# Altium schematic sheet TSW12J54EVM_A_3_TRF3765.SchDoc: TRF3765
size 431 x 279 mm; Date: Not shown in title block; ApprovedBy: Not shown in title block; CheckedBy: Not shown in title block; Author: Not shown in title block; CompanyName: Not shown in title block; DrawnBy: Not shown in title block; Engineer: Not shown in title block; Organization: Not shown in title block; Address1: Not shown in title block; Address2: Not shown in title block; Address3: Not shown in title block; Address4: Not shown in title block; DocumentNumber: 3; Revision: Use project parameter SCH_Rev; SheetNumber: 3; SheetTotal: 8; PageSetup: Record=PageOptions¦CenterHorizontal=True¦CenterVertical=True¦PrintScale=0.49¦XCorrection=1.00¦YCorrection=1.00¦PrintKind=0¦BorderSize=5000000¦LeftOffset=0¦BottomOffset=0¦Orientation=2¦PaperLength=1000¦PaperWidth=1000¦Scale=100¦PaperSource=15¦PrintQuality=600¦MediaType=1¦DitherType=10¦PaperKind=11x17¦PrintScaleMode=1
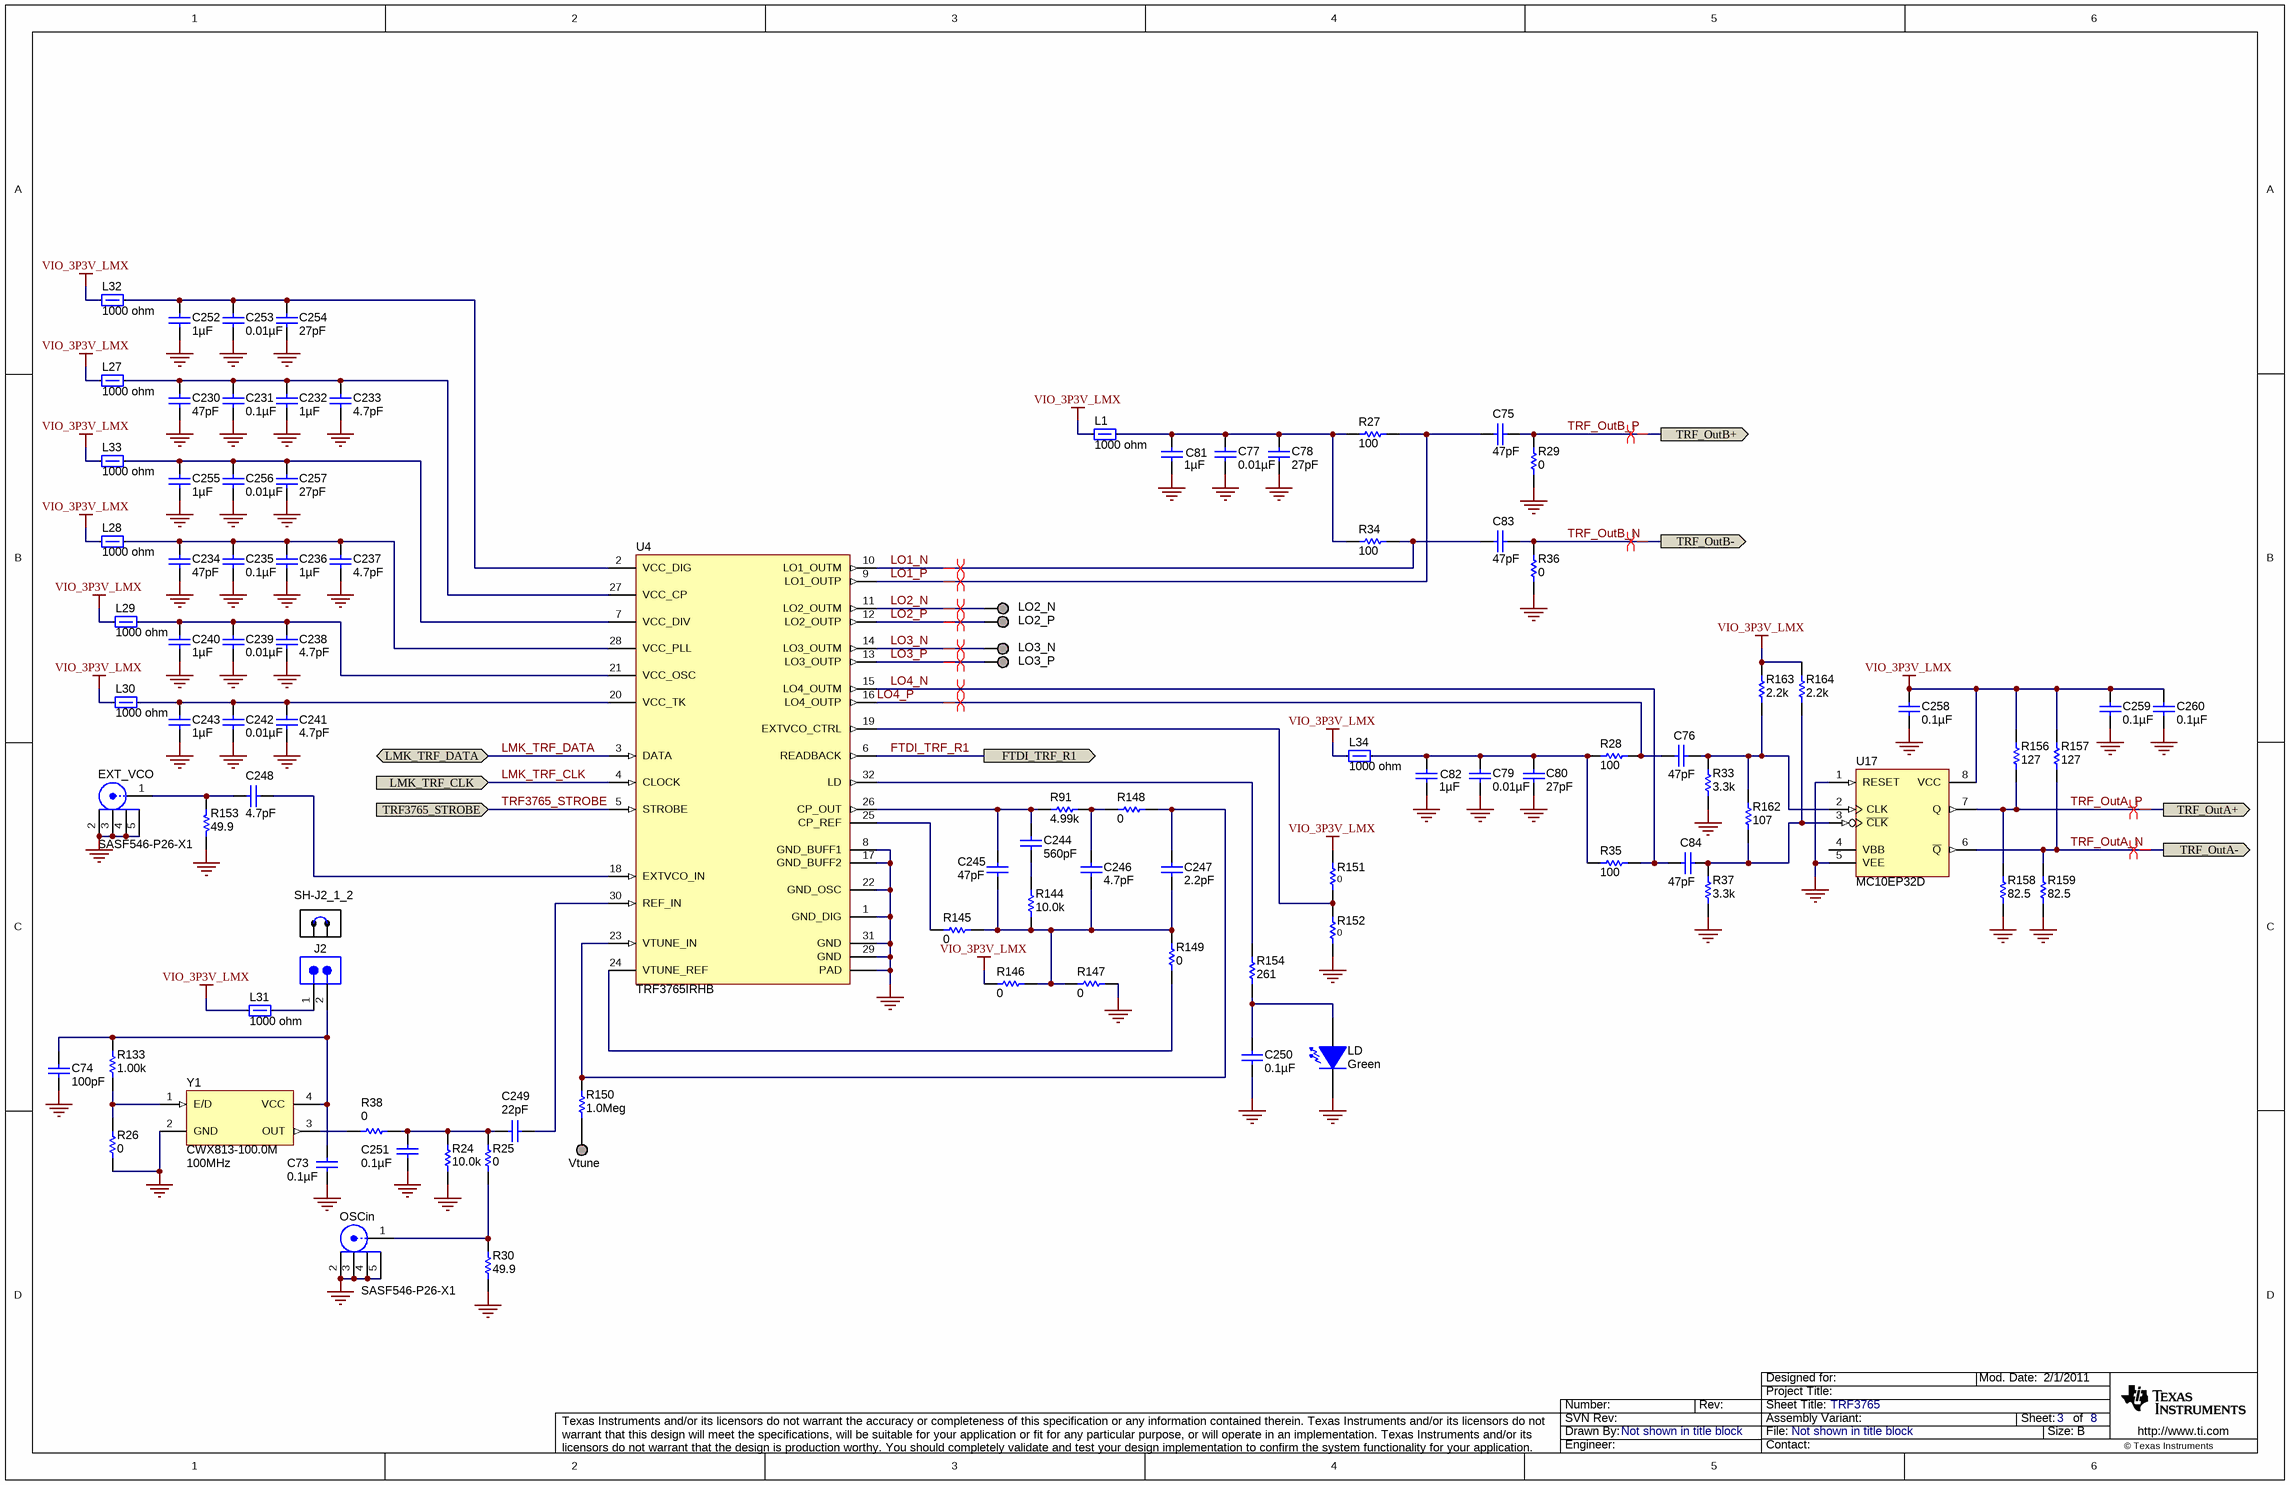
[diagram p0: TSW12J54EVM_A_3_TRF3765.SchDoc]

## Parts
C73  ValueDisplayed: 0.1µF  [0402L]  (hidden comment: C1005X5R1A104K)
C74  ValueDisplayed: 100pF  [0402L]  (hidden comment: GRM1555C1E101JA01D)
C75  ValueDisplayed: 47pF  [0402L]  (hidden comment: GRM1555C1H470JA01D)
C76  ValueDisplayed: 47pF  [0402L]  (hidden comment: GRM1555C1H470JA01D)
C77  ValueDisplayed: 0.01µF  [0402L]  (hidden comment: GRM155R71E103KA01D)
C78  ValueDisplayed: 27pF  [0402L]  (hidden comment: GRM1555C1H270JA01D)
C79  ValueDisplayed: 0.01µF  [0402L]  (hidden comment: GRM155R71E103KA01D)
C80  ValueDisplayed: 27pF  [0402L]  (hidden comment: GRM1555C1H270JA01D)
C81  ValueDisplayed: 1µF  [0402L]  (hidden comment: C1005X5R0J105M)
C82  ValueDisplayed: 1µF  [0402L]  (hidden comment: C1005X5R0J105M)
C83  ValueDisplayed: 47pF  [0402L]  (hidden comment: GRM1555C1H470JA01D)
C84  ValueDisplayed: 47pF  [0402L]  (hidden comment: GRM1555C1H470JA01D)
C230  ValueDisplayed: 47pF  [0603L]  (hidden comment: GRM1885C1H470JA01D)
C231  ValueDisplayed: 0.1µF  [0402L]  (hidden comment: C1005X5R1A104K)
C232  ValueDisplayed: 1µF  [0402L]  (hidden comment: C1005X5R0J105M)
C233  ValueDisplayed: 4.7pF  [0402L]  (hidden comment: GRM1555C1H4R7CA01D)
C234  ValueDisplayed: 47pF  [0603L]  (hidden comment: GRM1885C1H470JA01D)
C235  ValueDisplayed: 0.1µF  [0402L]  (hidden comment: C1005X5R1A104K)
C236  ValueDisplayed: 1µF  [0402L]  (hidden comment: C1005X5R0J105M)
C237  ValueDisplayed: 4.7pF  [0402L]  (hidden comment: GRM1555C1H4R7CA01D)
C238  ValueDisplayed: 4.7pF  [0402L]  (hidden comment: GRM1555C1H4R7CA01D)
C239  ValueDisplayed: 0.01µF  [0402L]  (hidden comment: GRM155R71E103KA01D)
C240  ValueDisplayed: 1µF  [0402L]  (hidden comment: C1005X5R0J105M)
C241  ValueDisplayed: 4.7pF  [0402L]  (hidden comment: GRM1555C1H4R7CA01D)
C242  ValueDisplayed: 0.01µF  [0402L]  (hidden comment: GRM155R71E103KA01D)
C243  ValueDisplayed: 1µF  [0402L]  (hidden comment: C1005X5R0J105M)
C244  ValueDisplayed: 560pF  [0402L]  (hidden comment: GRM1555C1H561JA01D)
C245  ValueDisplayed: 47pF  [0402L]  (hidden comment: GRM1555C1H470JA01D)
C246  ValueDisplayed: 4.7pF  [0402L]  (hidden comment: GRM1555C1H4R7CA01D)
C247  ValueDisplayed: 2.2pF  [0402L]  (hidden comment: GRM1555C1H2R2CA01D)
C248  ValueDisplayed: 4.7pF  [0402L]  (hidden comment: GRM1555C1H4R7CA01D)
C249  ValueDisplayed: 22pF  [0402L]  (hidden comment: GRM1555C1H220JA01D)
C250  ValueDisplayed: 0.1µF  [0402L]  (hidden comment: C1005X5R1A104K)
C251  ValueDisplayed: 0.1µF  [0402L]  (hidden comment: C1005X5R1A104K)
C252  ValueDisplayed: 1µF  [0402L]  (hidden comment: C1005X5R0J105M)
C253  ValueDisplayed: 0.01µF  [0402L]  (hidden comment: GRM155R71E103KA01D)
C254  ValueDisplayed: 27pF  [0402L]  (hidden comment: GRM1555C1H270JA01D)
C255  ValueDisplayed: 1µF  [0402L]  (hidden comment: C1005X5R0J105M)
C256  ValueDisplayed: 0.01µF  [0402L]  (hidden comment: GRM155R71E103KA01D)
C257  ValueDisplayed: 27pF  [0402L]  (hidden comment: GRM1555C1H270JA01D)
C258  ValueDisplayed: 0.1µF  [0402L]  (hidden comment: C1005X5R1A104K)
C259  ValueDisplayed: 0.1µF  [0402L]  (hidden comment: C1005X5R1A104K)
C260  ValueDisplayed: 0.1µF  [0402L]  (hidden comment: C1005X5R1A104K)
EXT_VCO  SASF546-P26-X1  [CONN_LTI_SASF546-P26-X1]
J2  TSW-102-07-G-S  [TSW-102-07-G-S]  (value not drawn)
L1  value 1000 ohm  [0402L]  (hidden comment: BLM15HG102SN1D)
L27  value 1000 ohm  [0402L]  (hidden comment: BLM15HG102SN1D)
L28  value 1000 ohm  [0402L]  (hidden comment: BLM15HG102SN1D)
L29  value 1000 ohm  [0402L]  (hidden comment: BLM15HG102SN1D)
L30  value 1000 ohm  [0402L]  (hidden comment: BLM15HG102SN1D)
L31  value 1000 ohm  [0402L]  (hidden comment: BLM15HG102SN1D)
L32  value 1000 ohm  [0402L]  (hidden comment: BLM15HG102SN1D)
L33  value 1000 ohm  [0402L]  (hidden comment: BLM15HG102SN1D)
L34  value 1000 ohm  [0402L]  (hidden comment: BLM15HG102SN1D)
LD  value Green  [LED_LTST-C190]  (hidden comment: LTST-C190GKT)
LO2_N  TESTPOINT  [TESTPOINT]  (value not drawn)  (no BOM)
LO2_P  TESTPOINT  [TESTPOINT]  (value not drawn)  (no BOM)
LO3_N  TESTPOINT  [TESTPOINT]  (value not drawn)  (no BOM)
LO3_P  TESTPOINT  [TESTPOINT]  (value not drawn)  (no BOM)
OSCin  SASF546-P26-X1  [CONN_LTI_SASF546-P26-X1]
R24  value 10.0k  [0402L]  (hidden comment: CRCW040210K0FKED)
R25  value 0  [0402L]  (hidden comment: ERJ-2GE0R00X)
R26  value 0  [0402L]  (hidden comment: ERJ-2GE0R00X)
R27  value 100  [0402L]  (hidden comment: CRCW0402100RFKED)
R28  value 100  [0402L]  (hidden comment: CRCW0402100RFKED)
R29  value 0  [0402L]  (hidden comment: ERJ-2GE0R00X)
R30  value 49.9  [0402L]  (hidden comment: CRCW040249R9FKED)
R33  value 3.3k  [0402L]  (hidden comment: CRCW04023K30JNED)
R34  value 100  [0402L]  (hidden comment: CRCW0402100RFKED)
R35  value 100  [0402L]  (hidden comment: CRCW0402100RFKED)
R36  value 0  [0402L]  (hidden comment: ERJ-2GE0R00X)
R37  value 3.3k  [0402L]  (hidden comment: CRCW04023K30JNED)
R38  value 0  [0402L]  (hidden comment: ERJ-2GE0R00X)
R91  value 4.99k  [0402L]  (hidden comment: CRCW04024K99FKED)
R133  value 1.00k  [0402L]  (hidden comment: CRCW04021K00FKED)
R144  value 10.0k  [0402L]  (hidden comment: CRCW040210K0FKED)
R145  value 0  [0402L]  (hidden comment: ERJ-2GE0R00X)
R146  value 0  [0402L]  (hidden comment: ERJ-2GE0R00X)
R147  value 0  [0402L]  (hidden comment: ERJ-2GE0R00X)
R148  value 0  [0402L]  (hidden comment: ERJ-2GE0R00X)
R149  value 0  [0402L]  (hidden comment: ERJ-2GE0R00X)
R150  value 1.0Meg  [0402L]  (hidden comment: CRCW04021M00JNED)
R151  value 0  [0603L]  (hidden comment: CRCW06030000Z0EA)
R152  value 0  [0603L]  (hidden comment: CRCW06030000Z0EA)
R153  value 49.9  [0402L]  (hidden comment: CRCW040249R9FKED)
R154  ValueDisplayed: 261  [0402L]  (hidden comment: CRCW0402261RFKED)
R156  value 127  [0402L]  (hidden comment: CRCW0402127RFKED)
R157  value 127  [0402L]  (hidden comment: CRCW0402127RFKED)
R158  value 82.5  [0402L]  (hidden comment: CRCW040282R5FKED)
R159  value 82.5  [0402L]  (hidden comment: CRCW040282R5FKED)
R162  value 107  [0402L]  (hidden comment: CRCW0402107RFKED)
R163  value 2.2k  [0402L]  (hidden comment: CRCW04022K20JNED)
R164  value 2.2k  [0402L]  (hidden comment: CRCW04022K20JNED)
SH-J2_1_2  SNT-100-BK-G  [SNT-100-BK-G]  (value not drawn)
U4  TRF3765IRHB  [RHB0032E]
U17  MC10EP32D  [751-06_N]
Vtune  TESTPOINT  [TESTPOINT]  (value not drawn)  (no BOM)
Y1  CWX813-100.0M  Frequency: 100MHz  [OSC_CWX]

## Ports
FTDI_TRF_R1, LMK_TRF_CLK, LMK_TRF_DATA (bidir), TRF3765_STROBE, TRF_OutA+ (out), TRF_OutA- (out), TRF_OutB+, TRF_OutB-

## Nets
GND: C73.1 C74.1 C77.2 C78.2 C79.2 C80.2 C81.2 C82.2 C230.2 C231.1 C232.2 C233.2 C234.2 C235.1 C236.2 C237.2 C238.2 C239.2 C240.2 C241.2 C242.2 C243.2 C250.1 C251.1 C252.2 C253.2 C254.2 C255.2 C256.2 C257.2 C258.1 C259.1 C260.1 EXT_VCO.2 EXT_VCO.3 EXT_VCO.4 EXT_VCO.5 LD.2(K) OSCin.2 OSCin.3 OSCin.4 OSCin.5 R24.1 R26.1 R29.1 R30.1 R33.1 R36.1 R37.1 R147.2 R152.2 R153.1 R158.1 R159.1 U4.1(GND_DIG) U4.8(GND_BUFF1) U4.17(GND_BUFF2) U4.22(GND_OSC) U4.29(GND) U4.31(GND) U4.33(PAD) U17.1(RESET) U17.5(VEE) Y1.2(GND)
VIO_3P3V_LMX: C258.2 C259.2 C260.2 L1.1 L27.1 L28.1 L29.1 L30.1 L31.1 L32.1 L33.1 L34.1 R146.1 R151.1 R156.2 R157.2 R163.2 R164.2 U17.8(VCC)
FTDI_TRF_R1: U4.6(READBACK) ; port FTDI_TRF_R1
LMK_TRF_CLK: U4.4(CLOCK) ; port LMK_TRF_CLK
LMK_TRF_DATA: U4.3(DATA) ; port LMK_TRF_DATA
LO1_N: C83.1 R34.2 U4.10(LO1_OUTM)
LO1_P: C75.1 R27.2 U4.9(LO1_OUTP)
LO2_N: LO2_N.1 U4.11(LO2_OUTM)
LO2_P: LO2_P.1 U4.12(LO2_OUTP)
LO3_N: LO3_N.1 U4.14(LO3_OUTM)
LO3_P: LO3_P.1 U4.13(LO3_OUTP)
LO4_N: C84.1 R35.2 U4.15(LO4_OUTM)
LO4_P: C76.1 R28.2 U4.16(LO4_OUTP)
TRF3765_STROBE: U4.5(STROBE) ; port TRF3765_STROBE
TRF_OutA_N: R157.1 R159.2 U17.6(~{Q}) ; port TRF_OutA-
TRF_OutA_P: R156.1 R158.2 U17.7(Q) ; port TRF_OutA+
TRF_OutB_N: C83.2 R36.2 ; port TRF_OutB-
TRF_OutB_P: C75.2 R29.2 ; port TRF_OutB+
NetC73_2: C73.2 C74.2 J2.2 R133.2 Y1.4(VCC)
NetC76_2: C76.2 R33.2 R162.2 R163.1 U17.2(CLK)
NetC77_1: C77.1 C78.1 C81.1 L1.2 R27.1 R34.1
NetC79_1: C79.1 C80.1 C82.1 L34.2 R28.1 R35.1
NetC84_2: C84.2 R37.2 R162.1 R164.1 U17.3(~{CLK})
NetC230_1: C230.1 C231.2 C232.1 C233.1 L27.2 U4.27(VCC_CP)
NetC234_1: C234.1 C235.2 C236.1 C237.1 L28.2 U4.28(VCC_PLL)
NetC238_1: C238.1 C239.1 C240.1 L29.2 U4.21(VCC_OSC)
NetC241_1: C241.1 C242.1 C243.1 L30.2 U4.20(VCC_TK)
NetC244_1: C244.1 C245.1 R91.1 U4.26(CP_OUT)
NetC244_2: C244.2 R144.2
NetC245_2: C245.2 C246.2 C247.2 R144.1 R145.2 R146.2 R147.1 R149.1
NetC246_1: C246.1 R91.2 R148.1
NetC247_1: C247.1 R148.2 R150.1 U4.23(VTUNE_IN)
NetC248_1: C248.1 U4.18(EXTVCO_IN)
NetC248_2: C248.2 EXT_VCO.1 R153.2
NetC249_1: C249.1 U4.30(REF_IN)
NetC249_2: C249.2 C251.2 R24.2 R25.2 R38.1
NetC250_2: C250.2 LD.1(A) R154.1
NetC252_1: C252.1 C253.1 C254.1 L32.2 U4.2(VCC_DIG)
NetC255_1: C255.1 C256.1 C257.1 L33.2 U4.7(VCC_DIV)
NetJ2_1: J2.1 L31.2
NetOSCin_1: OSCin.1 R25.1 R30.2
NetR26_2: R26.2 R133.1 Y1.1(E/D)
NetR38_2: R38.2 Y1.3(OUT)
NetR145_1: R145.1 U4.25(CP_REF)
NetR149_2: R149.2 U4.24(VTUNE_REF)
NetR150_2: R150.2 Vtune.1
NetR151_2: R151.2 R152.1 U4.19(EXTVCO_CTRL)
NetR154_2: R154.2 U4.32(LD)

Not connected (* = marked no-connect by the designer): U17 4(VBB)

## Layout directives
differential pair: LO1_N, LO1_P, LO2_N, LO2_P, LO3_N, LO3_P, LO4_N, LO4_P, TRF_OutA_N, TRF_OutA_P, TRF_OutB_N, TRF_OutB_P

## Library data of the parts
C73 C231 C235 C250 C251 C258-C260 = C1005X5R1A104K: CAP, CERM, 0.1uF, 10V, +/-10%, X5R, 0402; Manufacturer: TDK; Polarized: N; CompType: Capacitor; U/M: EA; Cap_F: 0.0000001; Tolerance_%: 10; ESR_Ohm: 0.0186; Value1: 0.0186 ohm; TaMin_C: -55; TaMax_C: 85; Cap_Case: 0402
C74 = GRM1555C1E101JA01D: CAP, CERM, 100pF, 25V, +/-5%, C0G/NP0, 0402; Manufacturer: MuRata; Cap_Case: 0402; Polarized: N; TaMax_C: 125; TaMin_C: -55; Tolerance_%: 5; VDC_V: 25; Cap_F: 0.0000000001; CompType: Capacitor; U/M: EA
C75 C76 C83 C84 C245 = GRM1555C1H470JA01D: CAP, CERM, 47pF, 50V, +/-5%, C0G/NP0, 0402; Manufacturer: MuRata; Polarized: N; CompType: Capacitor; U/M: EA; Cap_F: 0.000000000047; Tolerance_%: 5; Value1: Unknown; VDC_V: 50; TaMin_C: -55; TaMax_C: 125; Cap_Case: 0402
C77 C79 C239 C242 C253 C256 = GRM155R71E103KA01D: CAP, CERM, 0.01uF, 25V, +/-10%, X7R, 0402; Manufacturer: MuRata; Polarized: N; CompType: Capacitor; U/M: EA; Cap_F: 0.00000001; Tolerance_%: 10; Value1: Unknown; VDC_V: 25; TaMin_C: -55; TaMax_C: 125; Cap_Case: 0402
C78 C80 C254 C257 = GRM1555C1H270JA01D: CAP, CERM, 27pF, 50V, +/-5%, C0G/NP0, 0402; Manufacturer: MuRata; Polarized: N; CompType: Capacitor; U/M: EA; Cap_F: 0.000000000027; Tolerance_%: 5; Value1: Unknown; VDC_V: 50; TaMin_C: -55; TaMax_C: 125; Cap_Case: 0402
C81 C82 C232 C236 C240 C243 C252 C255 = C1005X5R0J105M: CAP, CERM, 1uF, 6.3V, +/-20%, X5R, 0402; Manufacturer: TDK; Polarized: N; CompType: Capacitor; U/M: EA; Cap_F: 0.000001; Tolerance_%: 20; ESR_Ohm: 0.0079; Value1: 0.0079 ohm; VDC_V: 6.3; TaMin_C: -55; TaMax_C: 85; Cap_Case: 0402
C230 C234 = GRM1885C1H470JA01D: CAP, CERM, 47pF, 50V, +/-5%, C0G/NP0, 0603; Manufacturer: MuRata; Polarized: N; CompType: Capacitor; U/M: EA; Cap_F: 0.000000000047; Tolerance_%: 5; Value1: Unknown; VDC_V: 50; TaMin_C: -55; TaMax_C: 125; Cap_Case: 0603
C233 C237 C238 C241 C246 C248 = GRM1555C1H4R7CA01D: CAP, CERM, 4.7pF, 50V, +/-5%, C0G/NP0, 0402; Manufacturer: MuRata; Polarized: N; CompType: Capacitor; U/M: EA; Cap_F: 0.0000000000047; Tolerance_%: 5; Value1: Unknown; VDC_V: 50; TaMin_C: -55; TaMax_C: 125; Cap_Case: 0402
C244 = GRM1555C1H561JA01D: CAP, CERM, 560pF, 50V, +/-5%, C0G/NP0, 0402; Manufacturer: MuRata; Polarized: N; CompType: Capacitor; U/M: EA; Cap_F: 0.00000000056; Tolerance_%: 5; Value1: Unknown; VDC_V: 50; TaMin_C: -55; TaMax_C: 125; Cap_Case: 0402
C247 = GRM1555C1H2R2CA01D: CAP, CERM, 2.2pF, 50V, +/-5%, C0G/NP0, 0402; Manufacturer: MuRata; Polarized: N; CompType: Capacitor; U/M: EA; Cap_F: 0.0000000000022; Tolerance_%: 5; Value1: Unknown; VDC_V: 50; TaMin_C: -55; TaMax_C: 125; Cap_Case: 0402
C249 = GRM1555C1H220JA01D: CAP, CERM, 22pF, 50V, +/-5%, C0G/NP0, 0402; Manufacturer: MuRata; Polarized: N; CompType: Capacitor; U/M: EA; Cap_F: 0.000000000022; Tolerance_%: 5; Value1: Unknown; VDC_V: 50; TaMin_C: -55; TaMax_C: 125; Cap_Case: 0402
EXT_VCO OSCin = SASF546-P26-X1: Connector, SMA,Vertical, Thru hole w/SMT center pin; Manufacturer: Lighthorse Technologies; U/M: EA
J2 = TSW-102-07-G-S: Header, TH, 100mil, 2x1, Gold plated, 230 mil above insulator; Manufacturer: Samtec, Inc.; U/M: EA
L1 L27-L34 = BLM15HG102SN1D: 0.25A Ferrite Bead, 1000 ohm @ 100MHz, SMD; Manufacturer: MuRata; Imax_A: 0.25; Irms: 0.25A @ C rise; Isat: 0.25A @ % inductance drop; DCR_ohm: 1.1; Value1: 1.1 ohm; ZTyp@100MHz_Ohm: 1000; U/M: EA
LD = LTST-C190GKT: LED, Green, SMD; Manufacturer: Lite-On; Vf_V: 2.1; Value2: 2.1V; Io_A: 0.02; Power_TotalModule: 0.1; Value1: 0.1W; U/M: EA
LO2_N LO2_P LO3_N LO3_P Vtune = TESTPOINT: TEST POINT.  No entry in BOM.
R24 R144 = CRCW040210K0FKED: RES, 10.0k ohm, 1%, 0.063W, 0402; Manufacturer: Vishay-Dale; CompType: Resistor; Res_ohm: 10000; Value_Code: 10k0; Tolerance_%: 1; Power_W: 0.063; VDC_V: 50; TempCo: 100 ppm/C; EIA_Code: E96; U/M: EA
R25 R26 R29 R36 R38 R145-R149 = ERJ-2GE0R00X: RES, 0 ohm, 5%, 0.063W, 0402; Manufacturer: Panasonic; CompType: Resistor; Value_Code: 0000; Tolerance_%: 5; Power_W: 0.063; VDC_V: 50; TempCo: 600 ppm/C; EIA_Code: E24; U/M: EA
R27 R28 R34 R35 = CRCW0402100RFKED: RES, 100 ohm, 1%, 0.063W, 0402; Manufacturer: Vishay-Dale; CompType: Resistor; Value_Code: 100R; Tolerance_%: 1; Power_W: 0.063; VDC_V: 50; TempCo: 100 ppm/C; EIA_Code: E96; U/M: EA
R30 R153 = CRCW040249R9FKED: RES, 49.9 ohm, 1%, 0.063W, 0402; Manufacturer: Vishay-Dale; CompType: Resistor; Value_Code: 49R9; Tolerance_%: 1; Power_W: 0.063; VDC_V: 50; TempCo: 100 ppm/C; EIA_Code: E96; U/M: EA
R33 R37 = CRCW04023K30JNED: RES, 3.3k ohm, 5%, 0.063W, 0402; Manufacturer: Vishay-Dale; CompType: Resistor; Res_ohm: 3300; Value_Code: 3k30; Tolerance_%: 5; Power_W: 0.063; VDC_V: 50; TempCo: 200 ppm/C; EIA_Code: E24; U/M: EA
R91 = CRCW04024K99FKED: RES, 4.99k ohm, 1%, 0.063W, 0402; Manufacturer: Vishay-Dale; CompType: Resistor; Res_ohm: 4990; Value_Code: 4k99; Tolerance_%: 1; Power_W: 0.063; VDC_V: 50; TempCo: 100 ppm/C; EIA_Code: E96; U/M: EA
R133 = CRCW04021K00FKED: RES, 1.00k ohm, 1%, 0.063W, 0402; Manufacturer: Vishay-Dale; CompType: Resistor; Res_ohm: 1000; Value_Code: 1k00; Tolerance_%: 1; Power_W: 0.063; VDC_V: 50; TempCo: 100 ppm/C; EIA_Code: E96; U/M: EA
R150 = CRCW04021M00JNED: RES, 1.0Meg ohm, 5%, 0.063W, 0402; Manufacturer: Vishay-Dale; CompType: Resistor; Res_ohm: 1000000; Value_Code: 1M00; Tolerance_%: 5; Power_W: 0.063; VDC_V: 50; TempCo: 200 ppm/C; EIA_Code: E24; U/M: EA
R151 R152 = CRCW06030000Z0EA: RES, 0 ohm, 5%, 0.1W, 0603; Manufacturer: Vishay-Dale; CompType: Resistor; Tolerance_%: 5; VDC_V: 75; Power_W: 0.1; U/M: EA; Value_Code: 0000; EIA_Code: E24
R154 = CRCW0402261RFKED: RES, 261, 1%, 0.063 W, 0402; Manufacturer: Vishay-Dale; CompType: Resistor; Value: 261; Value_Code: 261R; Tolerance_%: 1; Power_W: 0.063; Value2: 0.063W; VDC_V: 50; TempCo: 100 ppm/C; EIA_Code: E96; U/M: EA
R156 R157 = CRCW0402127RFKED: RES, 127 ohm, 1%, 0.063W, 0402; Manufacturer: Vishay-Dale; CompType: Resistor; Value_Code: 127R; Tolerance_%: 1; Power_W: 0.063; VDC_V: 50; TempCo: 100 ppm/C; EIA_Code: E96; U/M: EA
R158 R159 = CRCW040282R5FKED: RES, 82.5 ohm, 1%, 0.063W, 0402; Manufacturer: Vishay-Dale; CompType: Resistor; Value_Code: 82R5; Tolerance_%: 1; Power_W: 0.063; VDC_V: 50; TempCo: 100 ppm/C; EIA_Code: E96; U/M: EA
R162 = CRCW0402107RFKED: RES, 107 ohm, 1%, 0.063W, 0402; Manufacturer: Vishay-Dale; CompType: Resistor; Value_Code: 107R; Tolerance_%: 1; Power_W: 0.063; VDC_V: 50; TempCo: 100 ppm/C; EIA_Code: E96; U/M: EA
R163 R164 = CRCW04022K20JNED: RES, 2.2k ohm, 5%, 0.063W, 0402; Manufacturer: Vishay-Dale; CompType: Resistor; Res_ohm: 2200; Value_Code: 2k20; Tolerance_%: 5; Power_W: 0.063; VDC_V: 50; TempCo: 200 ppm/C; EIA_Code: E24; U/M: EA
SH-J2_1_2 = SNT-100-BK-G: Shunt, 100mil, Gold plated, Black; Manufacturer: Samtec, Inc.; Alternate Manufacturer: 3M; Alternate PartNumber: 969102-0000-DA; Value: 1x2; Note: You can "mate" this to a header by matching the designator.  i.e. use SH-J3 for header J3
U4 = TRF3765IRHB: Integer-N/Fractional-N PLL with Integrated VCO, RHB0032E; Alternate Manufacturer: None; Manufacturer: Texas Instruments; SymbolCreator: x0208326; CompType: IC; U/M: EA
U17 = MC10EP32D: Divide-by-2 Divider; Manufacturer: ON Semiconductor; PartNumber: MC10EP32DG
Y1 = CWX813-100.0M: OSC 100.0000MHZ 3.3V +-25PPM SMD; Manufacturer: Connor-Winfield; SymbolCreator: a0411947; CompType: Crystal; U/M: EA; TaMin_C: -20; TaMax_C: 70; Frequency Stability: ±25ppm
